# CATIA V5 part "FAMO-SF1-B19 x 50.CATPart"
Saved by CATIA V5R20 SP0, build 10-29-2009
Part number: FAMO-SF1-B19 x 50
Definition: NONE
Nomenclature: FAMO-SF1-B19 x 50
Source: Unknown
Description: FAMO-SF1-B19 x 50
Bounding box of the stored display mesh (mm): x -13 to 37, y -17 to 17, z -17 to 17
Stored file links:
  C:\Users\Utente\Desktop\IO LAVORO\3D X SITO CF\X SITO\FAMO\FAMO-SF1-B19 x 50.CATPart
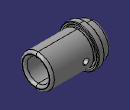
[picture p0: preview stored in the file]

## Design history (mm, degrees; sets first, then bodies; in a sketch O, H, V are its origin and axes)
Body1 "FAMO-SF1-B19 x 50" (main body)
  Solid1: solid without history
